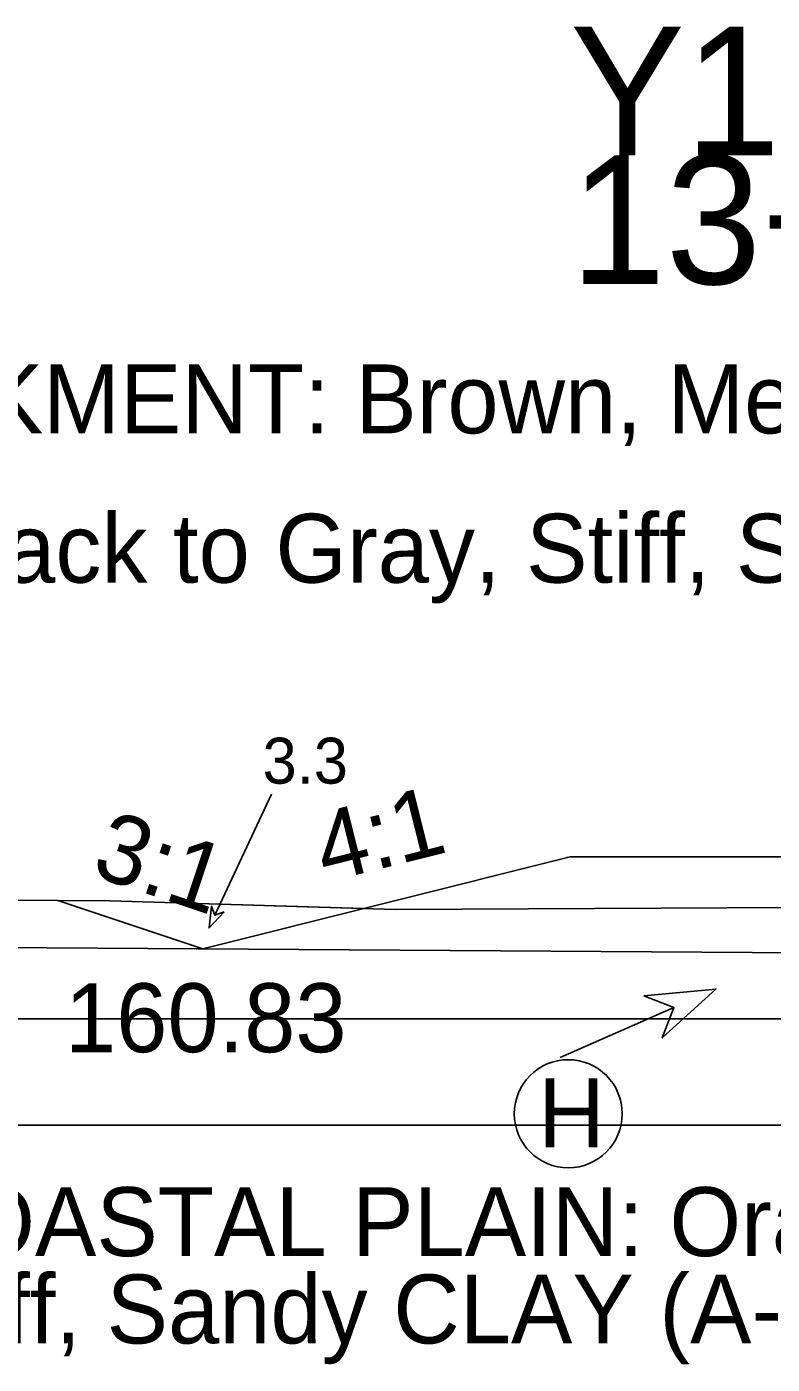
# Model space of a CAD drawing. Extents: x -516 to 303, y -10 to 5017.
# Drawn here: x 128.16 to 144.4, y 2994.79 to 3023.9 of the extents above; entities that cross this region are included whole.
import ezdxf

# ---------------------------------------------------------------- set-up
doc = ezdxf.new("R2010")
doc.units = 0
for name, color, linetype in [('Exist Cross Section Cell', 7, 'Continuous'), ('Exist XS Ground Line', 7, 'Continuous'), ('Misc Plan Tools Cell', 7, 'Continuous'), ('Prop CMT Slope Grass', 7, 'Continuous'), ('Prop Road Sect_ Material - Bubble + Leader + Bubble Tx', 7, 'Continuous'), ('Prop Road Sect_ Material - Contact (General - Major)', 7, 'Continuous'), ('Prop Road Sect_ Material - Contact (General - Minor)', 7, 'Continuous'), ('Prop Road Sect_ Material - Tx (Composite Desc)', 7, 'Continuous'), ('Prop Road Sect_ Misc - Drafting Aid (Tx - small)', 7, 'Continuous'), ('Prop Road Sect_ Recs - UUC (Outline)', 7, 'Continuous'), ('Prop Road Sect_ Recs - UUC (pattern)', 7, 'Continuous'), ('Prop XS Ditch Standard Text', 7, 'Continuous'), ('Prop XS Side Slope Text', 7, 'Continuous'), ('Scratch_Level_0', 7, 'Continuous')]:
    doc.layers.add(name, color=color, linetype=linetype)

msp = doc.modelspace()

# ---------------------------------------------------------------- linework, layer by layer
at = {"layer": 'Exist Cross Section Cell'}
msp.add_line((0, 3000), (150, 3000), dxfattribs=at)
at = {"layer": 'Exist XS Ground Line'}
msp.add_lwpolyline([(127.672, 3004.896), (129.972, 3004.88), (136.195, 3004.689), (149.203, 3004.752), (149.582, 3004.754), (150.284, 3004.733), (152.253, 3004.72), (152.849, 3004.709), (154.502, 3004.722), (155.155, 3004.726), (155.881, 3004.716), (157.807, 3004.691), (159.491, 3004.673), (160.537, 3004.661), (161.724, 3004.647), (162.792, 3004.634), (163.31, 3004.626), (163.611, 3004.623), (164.823, 3004.608), (165.597, 3004.599), (166.181, 3004.58)], dxfattribs=at)
at = {"layer": 'Misc Plan Tools Cell'}
msp.add_lwpolyline([(141.602, 3002.812), (143.177, 3002.958), (142.005, 3001.896), (142.261, 3002.555)], close=True, dxfattribs=at)
at = {"layer": 'Prop CMT Slope Grass'}
for p, q in [((140, 3005.834), (132, 3003.834)), ((146, 3005.834), (140, 3005.834)), ((132, 3003.834), (128.839, 3004.888))]:
    msp.add_line(p, q, dxfattribs=at)
at = {"layer": 'Prop Road Sect_ Material - Bubble + Leader + Bubble Tx'}
msp.add_line((139.786, 3001.466), (142.261, 3002.555), dxfattribs=at)
msp.add_circle((139.959, 3000.245), 1.176, dxfattribs=at)
at = {"layer": 'Prop Road Sect_ Material - Contact (General - Major)'}
msp.add_line((178.897, 3003.518), (2.457, 3004.705), dxfattribs=at)
at = {"layer": 'Prop Road Sect_ Material - Contact (General - Minor)'}
msp.add_line((120.547, 3002.312), (184.938, 3002.312), dxfattribs=at)
at = {"layer": 'Prop Road Sect_ Misc - Drafting Aid (Tx - small)'}
msp.add_line((133.492, 3007.202), (132.261, 3004.564), dxfattribs=at)
msp.add_lwpolyline([(132.462, 3004.637), (132.134, 3004.291), (132.189, 3004.765), (132.261, 3004.564)], close=True, dxfattribs=at)
at = {"layer": 'Prop Road Sect_ Recs - UUC (Outline)'}
msp.add_lwpolyline([(132, 3003.834), (135.506, 3004.711), (129.972, 3004.88), (128.839, 3004.888)], close=True, dxfattribs=at)
at = {"layer": 'Prop Road Sect_ Recs - UUC (pattern)'}
msp.add_lwpolyline([(132, 3003.834), (135.506, 3004.711), (129.972, 3004.88), (128.839, 3004.888), (132, 3003.834)], dxfattribs=at)

# ---------------------------------------------------------------- texts
at = {"layer": 'Exist Cross Section Cell'}
for s, p in [('Y1', (140, 3021.102)), ('13+00.00 / 1', (140, 3018.302))]:
    msp.add_text(s, height=2.8, dxfattribs=at).set_placement(p)
at = {"layer": 'Prop Road Sect_ Material - Tx (Composite Desc)'}
for s, p in [('ROADWAY EMBANKMENT: Brown, Medium Stiff to Stiff, Silty CLAY (A-7-6), Highly Plastic, Moist', (109.13, 3015.053)), ('COASTAL PLAIN: Black to Gray, Stiff, Sandy SILT (A-4), Moist (Black Creek Formation)', (109.055, 3011.803)), ('H', (139.306, 2999.513)), ('COASTAL PLAIN: Orange-Brown and Gray, Soft to Medium ', (125.332, 2997.147)), ('Stiff, Sandy CLAY (A-6), Moist to Wet (Black Creek Formation)', (125.332, 2995.246))]:
    msp.add_text(s, height=1.5, dxfattribs=at).set_placement(p)
at = {"layer": 'Prop Road Sect_ Misc - Drafting Aid (Tx - small)'}
msp.add_text('3.3', height=1, dxfattribs=at).set_placement((133.3, 3007.429))
at = {"layer": 'Prop XS Ditch Standard Text'}
msp.add_text('160.83', height=1.5, dxfattribs=at).set_placement((128.995, 3001.584))
at = {"layer": 'Prop XS Side Slope Text'}
for s, rotation, p in [('4:1', 14.0362, (134.665, 3005.273)), ('3:1', 341.5668, (129.529, 3005.448))]:
    msp.add_text(s, height=1.5, rotation=rotation, dxfattribs=at).set_placement(p)
at = {"layer": 'Scratch_Level_0'}
for s, p in [('LT_GS_OS_CTL', (139.894, 3005.824)), ('LT_Slope_Cut', (128.735, 3004.878)), ('LT_SS_Ditch_Base_Out', (131.821, 3003.824))]:
    msp.add_text(s, height=0.02, dxfattribs=at).set_placement(p)

doc.saveas('drawing.dxf')
